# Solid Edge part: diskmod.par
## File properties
Author: Deepak Maini
Template: NORMENG.PAR
Last saved by: CADCIM
Revision: 6
Application: Solid Edge
Accuracy: 0.99
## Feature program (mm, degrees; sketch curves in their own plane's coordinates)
sketch for "unnamed Protrusion 1" plane through (0, 0, 0) normal (0, 0, 1) x-axis (1, 0, 0)
  line (-25.2008, 3.175) -> (-20.6375, 3.175)
  arc centre (-20.6375, 0) radius 3.175 from (-20.6375, 3.175) to (-20.6375, -3.175) cw
  line (-25.2008, -3.175) -> (-20.6375, -3.175)
  arc centre (0, 0) radius 25.4 from (-3.175, -25.2008) to (-25.2008, -3.175) cw
  line (-3.175, -25.2008) -> (-3.175, -20.6375)
  arc centre (0, -20.6375) radius 3.175 from (-3.175, -20.6375) to (3.175, -20.6375) cw
  line (3.175, -25.2008) -> (3.175, -20.6375)
  arc centre (0, 0) radius 25.4 from (25.2008, -3.175) to (3.175, -25.2008) cw
  line (25.2008, -3.175) -> (20.6375, -3.175)
  arc centre (20.6375, 0) radius 3.175 from (20.6375, -3.175) to (20.6375, 3.175) cw
  line (25.2008, 3.175) -> (20.6375, 3.175)
  arc centre (0, 0) radius 25.4 from (3.175, 25.2008) to (25.2008, 3.175) cw
  line (3.175, 25.2008) -> (3.175, 20.6375)
  arc centre (0, 20.6375) radius 3.175 from (3.175, 20.6375) to (-3.175, 20.6375) cw
  line (-3.175, 25.2008) -> (-3.175, 20.6375)
  arc centre (0, 0) radius 25.4 from (-25.2008, 3.175) to (-3.175, 25.2008) cw
extrude "unnamed Protrusion 1" add finite 3.175 along +normal
sketch for "Hole_1" plane through (0, 0, 3.175) normal (0, 0, 1) x-axis (1, 0, 0)
  hole centre (0, 0) bore radius 12.7
hole "Hole_1" diameter 25.4 through
sketch for "ExtrudedProtrusion_2" plane through (0, 0, 3.175) normal (0, 0, 1) x-axis (1, 0, 0)
extrude "ExtrudedProtrusion_2" add finite 15.875 along +normal
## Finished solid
Body 1: solid body, 22 faces, 52 edges, 32 vertices.
  Faces by surface: plane 12, cylinder 10
  Edges by curve: line 32, circle 20
Bounding box of the edges (mm): 50.402 x 50.402 x 19.050, from (-25.2008, -25.2008, 0) to (25.2008, 25.2008, 19.05).
Cylindrical faces by radius (mm): R3.175 x4, R12.7 x1, R15.3815 x1, R25.4 x4
Planar faces by outward normal: +x 2, +y 2, +z 2, -x 2, -y 2, -z 2
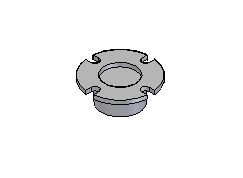
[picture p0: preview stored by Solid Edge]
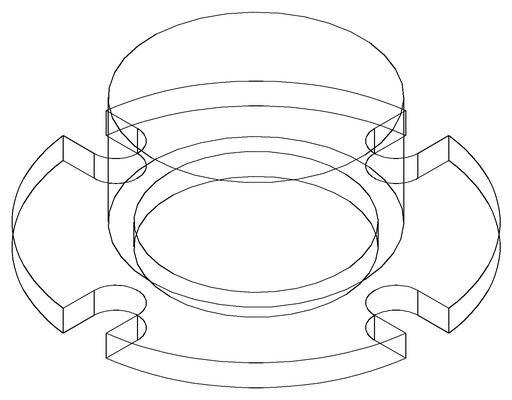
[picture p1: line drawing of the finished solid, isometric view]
